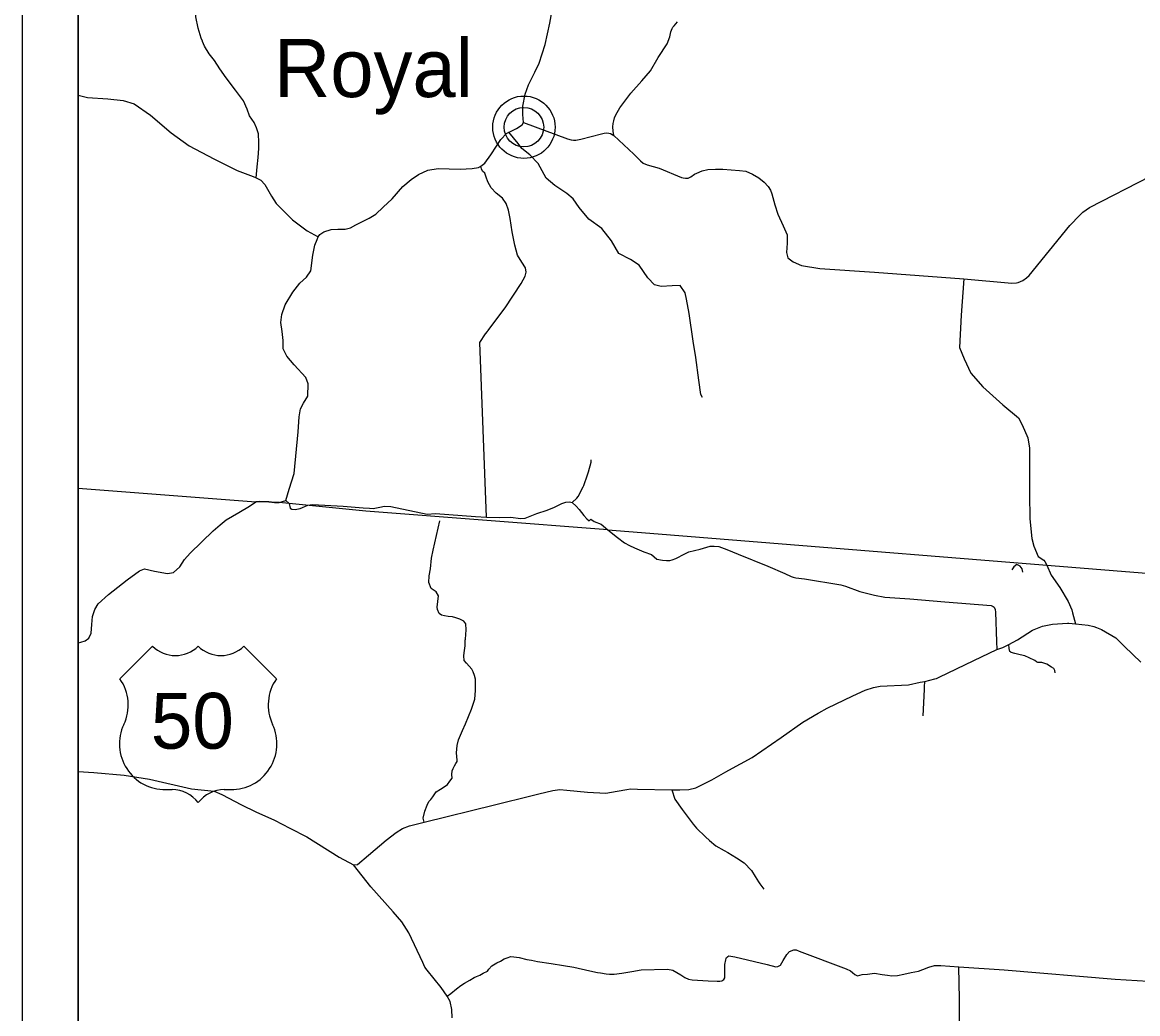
# Model space of a CAD drawing. Extents: x -22 to 431, y -18 to 160.
# Drawn here: x -21.978 to -19.98, y 26.152 to 27.928 of the extents above; entities that cross this region are included whole.
import ezdxf

# ---------------------------------------------------------------- set-up
doc = ezdxf.new("R2010")
doc.units = 0
for name, color, linetype in [('GM_X_Adjacent_County', 7, 'Continuous'), ('GM_X_Adjacent_County_Text', 7, 'Continuous'), ('GM_X_Airport_Location_Class_2', 7, 'Continuous'), ('GM_X_County_Road', 7, 'Continuous'), ('GM_X_County_ROW', 7, 'Continuous'), ('GM_X_Major_River_Text', 7, 'Continuous'), ('GM_X_Minor_Lake_Text', 7, 'Continuous'), ('GM_X_Minor_River', 7, 'Continuous'), ('GM_X_Minor_River_Text', 7, 'Continuous'), ('GM_X_Section', 7, 'Continuous'), ('GM_X_Township_Road', 7, 'Continuous'), ('GM_X_Township_Road_Text', 7, 'Continuous'), ('GM_X_Unincorporated_Location', 7, 'Continuous')]:
    doc.layers.add(name, color=color, linetype=linetype)

msp = doc.modelspace()

# ---------------------------------------------------------------- linework, layer by layer
at = {"layer": 'GM_X_Adjacent_County_Text'}
for points in [[(-21.5353, 27.0687), (-21.5263, 27.0678), (-21.5174, 27.0678), (-21.5056, 27.0709), (-21.4995, 27.0916), (-21.4905, 27.1195), (-21.4839, 27.1941), (-21.4821, 27.2208), (-21.4794, 27.2353), (-21.4738, 27.2454), (-21.4663, 27.2581), (-21.4655, 27.2803), (-21.4696, 27.2915), (-21.491, 27.3139), (-21.5042, 27.3295), (-21.5104, 27.3427), (-21.5105, 27.3575), (-21.5123, 27.374), (-21.5144, 27.3901), (-21.5128, 27.4045), (-21.5067, 27.4215), (-21.4929, 27.4441), (-21.4809, 27.4604), (-21.4685, 27.4713), (-21.4608, 27.4827), (-21.4571, 27.5108), (-21.4538, 27.5283), (-21.4494, 27.5386), (-21.4481, 27.5435), (-21.4447, 27.5473), (-21.4376, 27.5525), (-21.4245, 27.5566), (-21.4124, 27.5569), (-21.3993, 27.5574), (-21.3901, 27.5593), (-21.3803, 27.5649), (-21.3567, 27.5768), (-21.3447, 27.5843), (-21.3315, 27.5968), (-21.3154, 27.6115), (-21.296, 27.6337), (-21.281, 27.6461), (-21.268, 27.6551), (-21.2514, 27.6628), (-21.2331, 27.6655), (-21.1935, 27.6648), (-21.1723, 27.6658), (-21.1609, 27.6677), (-21.1566, 27.6697), (-21.1491, 27.6756), (-21.1386, 27.6905), (-21.1283, 27.7056), (-21.1208, 27.7178), (-21.1107, 27.7286), (-21.1063, 27.7309), (-21.1035, 27.7323), (-21.0924, 27.7375), (-21.0826, 27.7439), (-21.08, 27.7484), (-21.0811, 27.7626), (-21.0812, 27.7774), (-21.077, 27.7987), (-21.0713, 27.8154), (-21.0596, 27.8385), (-21.0519, 27.8545), (-21.0414, 27.8881), (-21.0327, 27.9261), (-21.0276, 27.9551)], [(-21.8776, 27.7972), (-21.8606, 27.7929), (-21.8242, 27.7907), (-21.7967, 27.7875), (-21.7775, 27.7814), (-21.7482, 27.7612), (-21.7112, 27.7295), (-21.679, 27.7066), (-21.6348, 27.6834), (-21.593, 27.6625), (-21.5641, 27.6514), (-21.5586, 27.6493), (-21.5503, 27.6452), (-21.5434, 27.6371), (-21.5313, 27.616), (-21.523, 27.603), (-21.4938, 27.5738), (-21.4673, 27.5543), (-21.4481, 27.5435)], [(-21.08, 27.7484), (-21.0012, 27.7187), (-20.9947, 27.7171), (-20.9904, 27.7166), (-20.9865, 27.7166), (-20.9777, 27.7183), (-20.9588, 27.7234), (-20.9407, 27.7278), (-20.9356, 27.729), (-20.931, 27.7295), (-20.9275, 27.729), (-20.9243, 27.7282), (-20.9213, 27.7269), (-20.9181, 27.7249), (-20.8828, 27.6914), (-20.8706, 27.6794), (-20.8657, 27.6756), (-20.8588, 27.6721), (-20.8375, 27.6662), (-20.7972, 27.6495), (-20.7944, 27.649), (-20.7899, 27.6483), (-20.7873, 27.6483), (-20.7853, 27.6486), (-20.7806, 27.6508), (-20.7739, 27.6554), (-20.77, 27.6577), (-20.7604, 27.6619), (-20.75, 27.6643), (-20.7363, 27.6647), (-20.7235, 27.6645), (-20.6935, 27.6623), (-20.6818, 27.6609), (-20.6698, 27.6559), (-20.6588, 27.6491), (-20.6493, 27.6412), (-20.6418, 27.6333), (-20.638, 27.6269), (-20.6353, 27.6205), (-20.63, 27.6008), (-20.6249, 27.5841), (-20.6149, 27.563), (-20.6078, 27.5471), (-20.6078, 27.532), (-20.609, 27.5154), (-20.6066, 27.506), (-20.5975, 27.4989), (-20.5825, 27.4918), (-20.5495, 27.4865), (-20.4519, 27.4803), (-20.2914, 27.4682), (-20.2964, 27.4029), (-20.2995, 27.3454), (-20.2908, 27.3248), (-20.2792, 27.2995), (-20.2574, 27.2749), (-20.2219, 27.2425), (-20.1937, 27.2191), (-20.1875, 27.2066), (-20.1769, 27.1834), (-20.1741, 27.1648), (-20.1739, 27.1233), (-20.1738, 27.0827), (-20.1732, 27.0383), (-20.1699, 27.0029), (-20.1664, 26.9893), (-20.1584, 26.9711), (-20.1485, 26.9645), (-20.1468, 26.9617)], [(-21.8776, 26.8165), (-21.8729, 26.8177), (-21.8653, 26.8197), (-21.8586, 26.8243), (-21.8543, 26.8336), (-21.8533, 26.849), (-21.8519, 26.8634), (-21.8478, 26.8758), (-21.842, 26.8862), (-21.8232, 26.9029), (-21.7896, 26.9288), (-21.7677, 26.9449), (-21.7589, 26.9489), (-21.7408, 26.9447), (-21.7179, 26.9402), (-21.7067, 26.942), (-21.6957, 26.9523), (-21.6872, 26.9654), (-21.6771, 26.9769), (-21.636, 27.0169), (-21.6234, 27.0275), (-21.6125, 27.0368), (-21.5897, 27.0495), (-21.5708, 27.061), (-21.5595, 27.0686), (-21.5534, 27.0695), (-21.5364, 27.0688), (-21.5353, 27.0687)], [(-20.1468, 26.9617), (-20.1429, 26.9554), (-20.1354, 26.9375), (-20.1199, 26.9151), (-20.1049, 26.89), (-20.0982, 26.8755), (-20.0968, 26.8699)], [(-20.0968, 26.8699), (-20.0919, 26.8504)]]:
    msp.add_lwpolyline(points, dxfattribs=at)
at = {"layer": 'GM_X_County_Road'}
for points in [[(-20.9181, 27.7249), (-20.9198, 27.7324), (-20.9203, 27.7402), (-20.9197, 27.7461), (-20.9186, 27.7511), (-20.917, 27.7563), (-20.9146, 27.762), (-20.9078, 27.7745), (-20.8879, 27.8009), (-20.8684, 27.8227), (-20.8528, 27.841), (-20.8388, 27.8647), (-20.8231, 27.8888), (-20.8181, 27.9017), (-20.8161, 27.9104), (-20.8153, 27.9135), (-20.8141, 27.9164), (-20.8125, 27.919), (-20.8104, 27.9216), (-20.8041, 27.9282)], [(-20.7594, 27.2558), (-20.7625, 27.261), (-20.7661, 27.2864), (-20.7714, 27.3272), (-20.7766, 27.3567), (-20.7836, 27.4063), (-20.788, 27.4319), (-20.7905, 27.4432), (-20.7994, 27.4564), (-20.8141, 27.4559), (-20.8334, 27.4546), (-20.8458, 27.4576), (-20.8576, 27.4698), (-20.8728, 27.4928), (-20.8886, 27.5027), (-20.9095, 27.5136), (-20.9224, 27.536), (-20.9396, 27.5583), (-20.963, 27.5749), (-20.9804, 27.5957), (-20.991, 27.6117), (-21.0026, 27.6213), (-21.0241, 27.6355), (-21.0394, 27.6483), (-21.0467, 27.6619), (-21.0538, 27.6749), (-21.0685, 27.6901), (-21.0834, 27.7018), (-21.0899, 27.7106), (-21.1063, 27.7309)], [(-21.1466, 27.0415), (-21.1583, 27.3543), (-21.148, 27.3698), (-21.1447, 27.3741), (-21.1441, 27.375)], [(-21.1843, 26.8211), (-21.1842, 26.8226), (-21.1828, 26.8394), (-21.1832, 26.8504), (-21.187, 26.8551), (-21.194, 26.8586), (-21.2016, 26.8609), (-21.207, 26.8626), (-21.2148, 26.8634), (-21.2218, 26.8643), (-21.2271, 26.8655), (-21.2309, 26.8688), (-21.2341, 26.8757), (-21.2346, 26.8803), (-21.2324, 26.9002), (-21.2366, 26.9074), (-21.2453, 26.9137), (-21.2495, 26.9242), (-21.2491, 26.936), (-21.2464, 26.949), (-21.2447, 26.9676), (-21.2418, 26.982), (-21.2299, 27.0348)], [(-21.2583, 26.4952), (-21.26, 26.5023), (-21.2569, 26.515), (-21.2527, 26.5255), (-21.2495, 26.532), (-21.246, 26.5355), (-21.2425, 26.5403), (-21.2363, 26.5493), (-21.2285, 26.5544), (-21.222, 26.5584), (-21.216, 26.5622), (-21.2122, 26.5682), (-21.208, 26.5741), (-21.2083, 26.5804), (-21.2077, 26.5868), (-21.2061, 26.5914), (-21.2036, 26.5961), (-21.2015, 26.6002), (-21.1988, 26.6035), (-21.1988, 26.6063), (-21.1999, 26.6195), (-21.1991, 26.6324), (-21.1965, 26.6425), (-21.1893, 26.659), (-21.1837, 26.671), (-21.1789, 26.6843), (-21.1733, 26.6975), (-21.1674, 26.7155), (-21.166, 26.7311), (-21.1658, 26.7446), (-21.1663, 26.751), (-21.1678, 26.7579), (-21.1701, 26.7643), (-21.1728, 26.769), (-21.182, 26.7801), (-21.1863, 26.7843), (-21.1871, 26.793), (-21.1863, 26.7983), (-21.1848, 26.8106), (-21.1843, 26.8211)]]:
    msp.add_lwpolyline(points, dxfattribs=at)
at = {"layer": 'GM_X_County_ROW'}
for points in [[(-20.2735, 26.7844), (-20.2324, 26.8041), (-20.2219, 26.808), (-20.2109, 26.813), (-20.1956, 26.8215), (-20.1688, 26.8391), (-20.1506, 26.8462), (-20.1327, 26.8494), (-20.1061, 26.8515)], [(-20.0544, 26.8438), (-20.0449, 26.84), (-20.0195, 26.8251), (-20.0069, 26.8126)], [(-20.0069, 26.8126), (-20.004, 26.8098), (-19.975, 26.7816)], [(-20.5513, 26.6908), (-20.5361, 26.6993), (-20.4904, 26.7212), (-20.4683, 26.7317), (-20.4536, 26.736), (-20.4417, 26.7388), (-20.391, 26.7413), (-20.3696, 26.7455), (-20.3613, 26.7472), (-20.3436, 26.7519)], [(-20.7123, 26.5883), (-20.6705, 26.6106), (-20.6185, 26.6466), (-20.5802, 26.6744), (-20.5527, 26.69), (-20.5513, 26.6908)], [(-21.8776, 26.5858), (-21.8498, 26.5841), (-21.7951, 26.5792), (-21.7499, 26.5718), (-21.6746, 26.555), (-21.6339, 26.5504), (-21.6201, 26.5445), (-21.5853, 26.5258), (-21.5593, 26.5134), (-21.5261, 26.4985), (-21.4983, 26.4845), (-21.4681, 26.4688), (-21.4102, 26.4323), (-21.3846, 26.4186)], [(-21.0528, 26.5455), (-21.0276, 26.5517), (-21.0153, 26.5534), (-21.0025, 26.5523), (-20.9653, 26.5486), (-20.9328, 26.5472), (-20.9125, 26.5505), (-20.8949, 26.5538), (-20.8883, 26.5546), (-20.8761, 26.5543), (-20.8147, 26.5527), (-20.8002, 26.5528), (-20.7842, 26.5536), (-20.7718, 26.5567), (-20.7429, 26.5711), (-20.7177, 26.5854), (-20.7123, 26.5883)], [(-21.3846, 26.4186), (-21.3774, 26.4194), (-21.3575, 26.4358), (-21.3259, 26.4626), (-21.3082, 26.4764), (-21.2968, 26.4839), (-21.2843, 26.4886), (-21.2583, 26.4952), (-21.1318, 26.5261), (-21.0646, 26.5426), (-21.0528, 26.5455)], [(-21.208, 26.1446), (-21.2084, 26.1594), (-21.2117, 26.1739), (-21.2166, 26.1836), (-21.2276, 26.1987), (-21.2529, 26.2302), (-21.2568, 26.2354), (-21.2606, 26.2436), (-21.2854, 26.297), (-21.2979, 26.3167), (-21.3135, 26.3346), (-21.3538, 26.3795), (-21.3846, 26.4186)]]:
    msp.add_lwpolyline(points, dxfattribs=at)
at = {"layer": 'GM_X_Major_River_Text'}
for p, q in [((-21.8776, 27.0935), (-21.5595, 27.0686)), ((-21.5534, 27.0695), (-21.5595, 27.0686)), ((-21.5595, 27.0686), (-21.5534, 27.0695)), ((-21.5364, 27.0688), (-21.5534, 27.0695)), ((-21.5534, 27.0695), (-21.5364, 27.0688)), ((-21.5263, 27.0678), (-21.5364, 27.0688)), ((-21.5364, 27.0688), (-21.5263, 27.0678)), ((-21.5174, 27.0678), (-21.5263, 27.0678)), ((-21.5263, 27.0678), (-21.5174, 27.0678)), ((-21.3625, 27.0521), (-21.5174, 27.0678)), ((-20.9293, 27.0189), (-21.3625, 27.0521)), ((-20.9293, 27.0189), (-20.8538, 27.0124)), ((-20.8538, 27.0124), (-19.8086, 26.9285))]:
    msp.add_line(p, q, dxfattribs=at)
at = {"layer": 'GM_X_Minor_Lake_Text'}
for points in [[(-20.1061, 26.8515), (-20.1036, 26.8517), (-20.0919, 26.8504), (-20.0688, 26.848), (-20.0591, 26.8457), (-20.0544, 26.8438)], [(-20.3436, 26.7519), (-20.3409, 26.7526), (-20.3361, 26.7545), (-20.2735, 26.7844)]]:
    msp.add_lwpolyline(points, dxfattribs=at)
at = {"layer": 'GM_X_Minor_River'}
msp.add_lwpolyline([(-21.8776, 27.178), (-21.8771, 27.1833), (-21.8773, 27.189), (-21.8776, 27.1909)], dxfattribs=at)
at = {"layer": 'GM_X_Minor_River_Text'}
for points in [[(-21.6551, 27.8934), (-21.6552, 27.8937), (-21.6575, 27.8994), (-21.6628, 27.9174), (-21.6666, 27.9376), (-21.6673, 27.9558), (-21.6615, 27.9723), (-21.6569, 27.9866), (-21.657, 27.9963), (-21.6538, 28.0179), (-21.6515, 28.0348), (-21.6511, 28.0397), (-21.6535, 28.045), (-21.6674, 28.0603), (-21.6717, 28.0705), (-21.6778, 28.0981), (-21.6832, 28.1144), (-21.6898, 28.1297), (-21.7, 28.1491), (-21.7063, 28.1616), (-21.711, 28.1729), (-21.7147, 28.1822)], [(-21.5586, 27.6493), (-21.5573, 27.6685), (-21.5551, 27.6856), (-21.5541, 27.7017), (-21.554, 27.7123), (-21.5549, 27.7277), (-21.5581, 27.7388), (-21.5627, 27.7483), (-21.5706, 27.76), (-21.5748, 27.7719), (-21.5818, 27.7868), (-21.5958, 27.8062), (-21.6126, 27.8279), (-21.6237, 27.8441), (-21.6335, 27.859), (-21.6431, 27.8714), (-21.6515, 27.8848), (-21.6551, 27.8934)], [(-21.1441, 27.375), (-21.1132, 27.4165), (-21.0846, 27.46), (-21.0773, 27.4727), (-21.0753, 27.4803), (-21.0763, 27.4877), (-21.083, 27.4981), (-21.0907, 27.5108), (-21.0958, 27.5287), (-21.1003, 27.5522), (-21.1043, 27.5764), (-21.1071, 27.591), (-21.1113, 27.6029), (-21.1179, 27.6124), (-21.1293, 27.6217), (-21.1379, 27.6313), (-21.1442, 27.6419), (-21.1468, 27.6504), (-21.1493, 27.6576), (-21.1537, 27.6612), (-21.1552, 27.6651), (-21.1566, 27.6697)], [(-20.2914, 27.4682), (-20.206, 27.4603), (-20.1974, 27.4612), (-20.1942, 27.4618), (-20.1861, 27.4653), (-20.1792, 27.47), (-20.1748, 27.4739), (-20.1021, 27.5638), (-20.0839, 27.5823), (-20.0787, 27.5875), (-20.0664, 27.5959), (-19.9576, 27.6518), (-19.9366, 27.6623)], [(-20.9932, 27.0674), (-20.9847, 27.0755), (-20.9825, 27.0782), (-20.9735, 27.0958), (-20.9723, 27.0982), (-20.9655, 27.117), (-20.9637, 27.1223), (-20.9591, 27.14), (-20.959, 27.1439)], [(-21.5056, 27.0709), (-21.4997, 27.066)], [(-21.4997, 27.066), (-21.4979, 27.0574), (-21.4949, 27.0559), (-21.4892, 27.0552), (-21.4803, 27.0568), (-21.4666, 27.0627)], [(-21.4666, 27.0627), (-21.458, 27.0639), (-21.403, 27.0613), (-21.3672, 27.0583), (-21.356, 27.0577), (-21.3494, 27.0569), (-21.3375, 27.0591), (-21.3288, 27.0609), (-21.3179, 27.0606), (-21.2526, 27.0469), (-21.2375, 27.0476), (-21.166, 27.0425), (-21.1466, 27.0415), (-21.1225, 27.041), (-21.103, 27.0413), (-21.0853, 27.0388), (-21.0772, 27.0394), (-21.0563, 27.0481), (-21.0377, 27.054), (-21.0245, 27.0594), (-21.0113, 27.0658), (-21.0043, 27.0681), (-20.9975, 27.0689), (-20.9932, 27.0674)], [(-20.9932, 27.0674), (-20.9859, 27.061), (-20.9802, 27.055), (-20.9721, 27.0445), (-20.967, 27.0384), (-20.9628, 27.0347), (-20.9593, 27.0377), (-20.9538, 27.0338), (-20.9411, 27.0288), (-20.9293, 27.0189)], [(-20.9293, 27.0189), (-20.9118, 27.0049), (-20.8993, 26.9956), (-20.8903, 26.9903), (-20.8813, 26.9861), (-20.8646, 26.9795), (-20.8509, 26.9745), (-20.8412, 26.9661), (-20.8315, 26.9645), (-20.8241, 26.9636), (-20.8183, 26.9638), (-20.8139, 26.9646), (-20.8073, 26.9673), (-20.7913, 26.9756), (-20.7841, 26.9793), (-20.7637, 26.9842), (-20.7456, 26.9892), (-20.7386, 26.9895), (-20.7303, 26.9888), (-20.716, 26.9836), (-20.6955, 26.9749), (-20.6427, 26.9537), (-20.6119, 26.9403), (-20.6008, 26.9353), (-20.597, 26.9338), (-20.5925, 26.9325), (-20.5771, 26.9307), (-20.5121, 26.9202), (-20.5038, 26.918), (-20.4777, 26.9082), (-20.4517, 26.9014), (-20.4331, 26.8981), (-20.3884, 26.8953), (-20.3257, 26.8897), (-20.2427, 26.883), (-20.2389, 26.8815), (-20.2374, 26.88), (-20.2353, 26.8757), (-20.235, 26.8713), (-20.2329, 26.8187)], [(-20.2329, 26.8187), (-20.2324, 26.8041)], [(-20.2075, 26.7994), (-20.2091, 26.8008), (-20.2104, 26.8061), (-20.2109, 26.813)], [(-20.1279, 26.7626), (-20.1287, 26.7665), (-20.1308, 26.7701), (-20.1346, 26.7729), (-20.143, 26.778), (-20.1519, 26.7811), (-20.1591, 26.7809), (-20.1618, 26.782), (-20.1648, 26.7846), (-20.1747, 26.7895), (-20.1825, 26.7927), (-20.1906, 26.7949), (-20.2003, 26.7971), (-20.2068, 26.7987), (-20.2075, 26.7994)], [(-20.3618, 26.7376), (-20.3613, 26.7472)], [(-20.3647, 26.6852), (-20.362, 26.7329)], [(-20.362, 26.7329), (-20.3618, 26.7376)], [(-20.8147, 26.5527), (-20.809, 26.536), (-20.7963, 26.5178), (-20.7888, 26.508), (-20.7766, 26.4916), (-20.7706, 26.4842), (-20.7542, 26.4688), (-20.7472, 26.4624), (-20.7355, 26.4528), (-20.7211, 26.4442), (-20.7142, 26.4405), (-20.6988, 26.4311), (-20.6851, 26.422), (-20.6721, 26.4086), (-20.6656, 26.398), (-20.6596, 26.388), (-20.6569, 26.3844), (-20.6497, 26.3748)], [(-21.2166, 26.1836), (-21.2103, 26.188), (-21.1999, 26.1966), (-21.1926, 26.2027), (-21.186, 26.2069), (-21.1762, 26.2118), (-21.1685, 26.2166), (-21.1641, 26.2189), (-21.1581, 26.2212), (-21.1521, 26.2243), (-21.1445, 26.2279), (-21.1421, 26.2319), (-21.1368, 26.2375), (-21.128, 26.2431), (-21.1214, 26.2463), (-21.1148, 26.2502), (-21.1095, 26.2523), (-21.1027, 26.2543), (-21.0972, 26.2537), (-21.0879, 26.2527), (-21.0742, 26.249), (-21.0659, 26.2481), (-21.0549, 26.2457), (-21.0306, 26.242), (-21.0088, 26.2384), (-20.9903, 26.2355), (-20.9616, 26.2289), (-20.9479, 26.226), (-20.9423, 26.2254), (-20.9324, 26.2231), (-20.9261, 26.2225), (-20.9178, 26.2226), (-20.9042, 26.2244), (-20.8862, 26.2274), (-20.8694, 26.2308), (-20.8225, 26.2317), (-20.8126, 26.2299), (-20.7983, 26.2217), (-20.7911, 26.2166), (-20.7846, 26.214), (-20.778, 26.2124), (-20.7494, 26.2111), (-20.7333, 26.2105), (-20.7284, 26.2103), (-20.725, 26.2109), (-20.7212, 26.213), (-20.7199, 26.2161), (-20.7198, 26.2222), (-20.7195, 26.2402), (-20.7179, 26.2487), (-20.7175, 26.2508), (-20.7164, 26.2529), (-20.7151, 26.2539), (-20.7142, 26.2545), (-20.7127, 26.2556), (-20.702, 26.2536), (-20.644, 26.2399), (-20.6282, 26.2362), (-20.6248, 26.2366), (-20.6226, 26.2378), (-20.6199, 26.2391), (-20.6154, 26.2471), (-20.6089, 26.2578), (-20.6037, 26.2631), (-20.5963, 26.2664), (-20.5917, 26.2663), (-20.5866, 26.264), (-20.5023, 26.2325), (-20.4947, 26.2289), (-20.491, 26.2259), (-20.4867, 26.2222), (-20.4821, 26.2196), (-20.4736, 26.2219), (-20.4639, 26.2226), (-20.4518, 26.2244), (-20.438, 26.222), (-20.4283, 26.2208), (-20.4207, 26.2199), (-20.4107, 26.2205), (-20.3992, 26.2225), (-20.3858, 26.2255), (-20.3731, 26.2282), (-20.3648, 26.231), (-20.3542, 26.2354), (-20.344, 26.2381), (-20.333, 26.2386), (-20.3006, 26.2362), (-20.2195, 26.2304), (-20.0208, 26.214), (-19.9615, 26.2105)], [(-20.2916, 25.9769), (-20.2886, 25.9994), (-20.2849, 26.0306), (-20.2894, 26.0723), (-20.2936, 26.0931), (-20.2979, 26.1158), (-20.2996, 26.1363), (-20.2996, 26.1782), (-20.3006, 26.2362)]]:
    msp.add_lwpolyline(points, dxfattribs=at)
at = {"layer": 'GM_X_Section'}
for p, q in [((-21.9776, 29.1642), (-21.9776, 22.1642)), ((-21.8776, 29.0642), (-21.8776, 22.2642)), ((-21.8776, 22.2642), (-21.8776, 29.0642))]:
    msp.add_line(p, q, dxfattribs=at)
at = {"layer": 'GM_X_Township_Road'}
for radius in [0.0558, 0.0354]:
    msp.add_circle((-21.0794, 27.7398), radius, dxfattribs=at)
at = {"layer": 'GM_X_Township_Road_Text'}
msp.add_lwpolyline([(-20.1859, 26.9426), (-20.1871, 26.9487), (-20.1905, 26.9534), (-20.1968, 26.9568), (-20.2022, 26.9521), (-20.206, 26.9471)], dxfattribs=at)
at = {"layer": 'GM_X_Unincorporated_Location'}
for p, q in [((-21.7443, 26.8102), (-21.8027, 26.7518)), ((-21.5226, 26.7518), (-21.5809, 26.8102)), ((-21.721, 26.5534), (-21.7093, 26.5534)), ((-21.6159, 26.5534), (-21.6043, 26.5534))]:
    msp.add_line(p, q, dxfattribs=at)
for centre, radius, start, end in [((-21.7035, 26.8519), 0.0584, 225.573, 314.427), ((-21.6218, 26.8519), 0.0584, 225.573, 314.427), ((-21.8696, 26.705), 0.0817, 334.5471, 35.0009), ((-21.4556, 26.705), 0.0817, 144.9991, 205.4529), ((-21.7219, 26.6351), 0.0817, 154.8319, 270.6383), ((-21.6034, 26.6351), 0.0817, 269.3617, 25.1681), ((-21.7093, 26.495), 0.0584, 36.8699, 90), ((-21.6159, 26.495), 0.0584, 90, 143.1301)]:
    msp.add_arc(centre, radius, start, end, dxfattribs=at)

# ---------------------------------------------------------------- texts
at = {"layer": 'GM_X_Adjacent_County'}
msp.add_text('Royal', height=0.10417, rotation=0, dxfattribs=at).set_placement((-21.5267, 27.7937))
at = {"layer": 'GM_X_Airport_Location_Class_2'}
msp.add_text('50', height=0.1, dxfattribs=at).set_placement((-21.7475, 26.6266))

doc.saveas('drawing.dxf')
